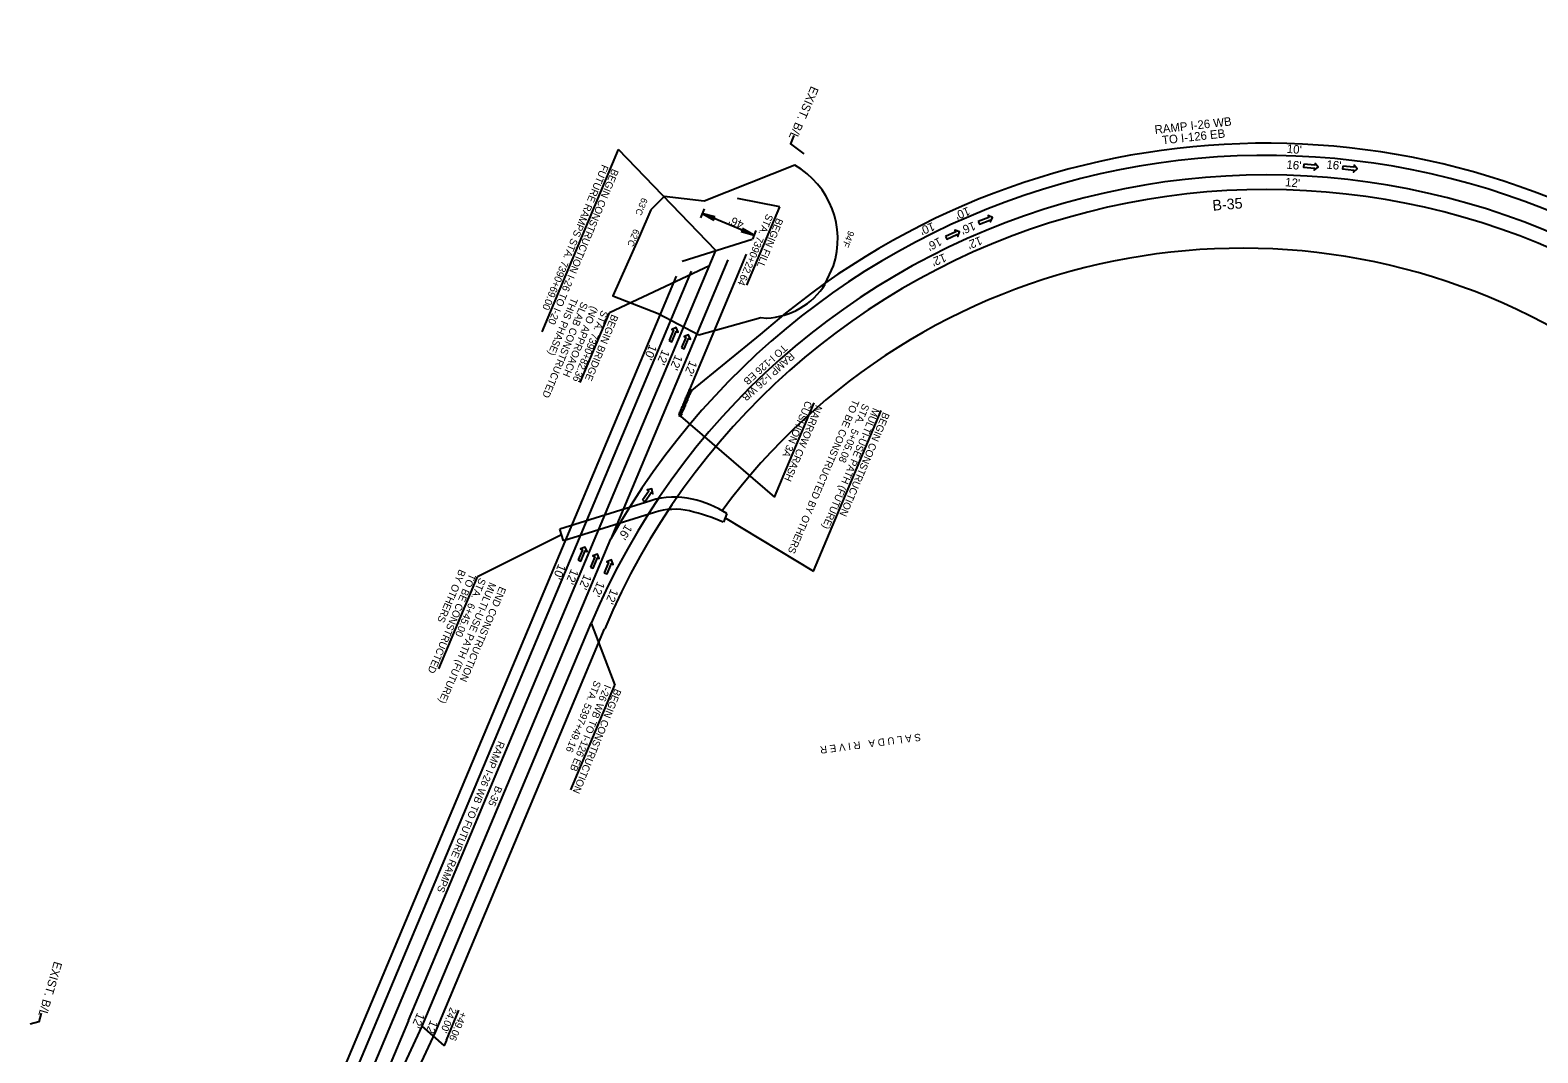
# Model space of a CAD drawing. Extents: x 1966090 to 1975830, y 788086 to 801233.
# Drawn here: x 1968411 to 1969648, y 796844 to 797683 of the extents above; entities that cross this region are included whole.
import ezdxf

# ---------------------------------------------------------------- set-up
doc = ezdxf.new("R2010")
doc.units = 0
for name, color, linetype in [('BR_PRESTRESSED BEAM', 7, 'Continuous'), ('BR_PROPOSED_DRAINAGE', 7, 'Continuous'), ('RD_EX_Driveway_txCode', 7, 'Continuous'), ('RD_EX_SU_Gas', 7, 'Continuous'), ('RD_EX_SU_H2O', 7, 'Continuous'), ('RD_EX_SU_SwpLmt', 7, 'Continuous'), ('RD_EX_TX_BldgApp_ELEV', 7, 'Continuous'), ('RD_EX_TX_Dam_ELEV', 7, 'Continuous'), ('RD_GT_Surcharge', 7, 'Continuous'), ('RD_PD_PaveShd', 7, 'Continuous'), ('RD_Sketch6', 7, 'Continuous'), ('RD_Sketch8', 7, 'Continuous')]:
    doc.layers.add(name, color=color, linetype=linetype)

msp = doc.modelspace()

# ---------------------------------------------------------------- linework, layer by layer
at = {"layer": 'BR_PRESTRESSED BEAM'}
msp.add_line((1968951.7, 797388.6), (1968953.5, 797387.8), dxfattribs=at)
at = {"layer": 'BR_PROPOSED_DRAINAGE'}
for p, q in [((1968931, 797546.9), (1968920.1, 797536)), ((1968920.1, 797536), (1968910.7, 797514.3)), ((1969063.1, 797475.1), (1969069.8, 797489.9)), ((1968926, 797450.8), (1968959.4, 797433.4))]:
    msp.add_line(p, q, dxfattribs=at)
for points in [[(1969038.3, 797572.5), (1968963.9, 797543.2), (1968931, 797546.9)], [(1968910.7, 797514.3), (1968888.9, 797465.3), (1968926, 797450.8)], [(1968959.4, 797433.4), (1969010.3, 797447.6), (1969015.1, 797447)]]:
    msp.add_lwpolyline(points, dxfattribs=at)
for centre, radius, start, end in [((1969003.7, 797512), 69.7, 341.4906, 60.2558), ((1969012.3, 797507), 60, 272.7088, 327.863)]:
    msp.add_arc(centre, radius, start, end, dxfattribs=at)
at = {"layer": 'RD_EX_Driveway_txCode'}
for p, q in [((1968963.9, 797536.7), (1968960.8, 797529.3)), ((1969004.8, 797515.2), (1968962.3, 797533)), ((1969006.3, 797518.9), (1969003.4, 797512))]:
    msp.add_line(p, q, dxfattribs=at)
for points in [[(1969455.6, 797573.4), (1969455.4, 797571), (1969464.5, 797570.1), (1969464.3, 797568.5), (1969467.4, 797571), (1969464.9, 797574.1), (1969464.7, 797572.5)], [(1969487.7, 797571.9), (1969487.4, 797569.5), (1969496.6, 797568.6), (1969496.4, 797567), (1969499.5, 797569.5), (1969497, 797572.6), (1969496.8, 797571)], [(1969188.7, 797526.5), (1969189.6, 797524.3), (1969198.1, 797527.6), (1969198.7, 797526.1), (1969200.3, 797529.8), (1969196.7, 797531.4), (1969197.3, 797529.8)], [(1969161.8, 797514.1), (1969162.8, 797511.9), (1969171.2, 797515.7), (1969171.8, 797514.2), (1969173.3, 797518), (1969169.5, 797519.4), (1969170.2, 797517.9)], [(1968935.2, 797428.7), (1968937.4, 797427.7), (1968941, 797436.2), (1968942.5, 797435.6), (1968941, 797439.3), (1968937.3, 797437.8), (1968938.8, 797437.1)], [(1968945.3, 797422.9), (1968947.5, 797421.9), (1968951, 797430.4), (1968952.5, 797429.8), (1968951, 797433.5), (1968947.3, 797431.9), (1968948.8, 797431.3)], [(1968913.3, 797297.6), (1968915.3, 797296.3), (1968920.4, 797303.9), (1968921.8, 797302.9), (1968921, 797306.9), (1968917.1, 797306.1), (1968918.4, 797305.2)], [(1968860.5, 797248.6), (1968862.7, 797247.7), (1968866.3, 797256.1), (1968867.8, 797255.5), (1968866.2, 797259.2), (1968862.5, 797257.7), (1968864, 797257)], [(1968870.6, 797242.8), (1968872.8, 797241.8), (1968876.3, 797250.3), (1968877.8, 797249.7), (1968876.3, 797253.4), (1968872.6, 797251.9), (1968874.1, 797251.2)], [(1968881.9, 797238), (1968884.2, 797237.1), (1968887.7, 797245.6), (1968889.2, 797244.9), (1968887.7, 797248.6), (1968884, 797247.1), (1968885.5, 797246.5)]]:
    msp.add_lwpolyline(points, close=True, dxfattribs=at)
at = {"layer": 'RD_EX_SU_Gas'}
for p, q in [((1968592.6, 796594.5), (1968973.4, 797502.5)), ((1968721.4, 796870.7), (1968887.2, 797265.9)), ((1968721.4, 796870.7), (1968605.4, 796594))]:
    msp.add_line(p, q, dxfattribs=at)
msp.add_arc((1981199.2, 806823), 14512, 217.23394, 219.56622, dxfattribs=at)
at = {"layer": 'RD_EX_TX_BldgApp_ELEV'}
for p, q in [((1968951.6, 797388.6), (1968950.9, 797386.1)), ((1968953.6, 797387.8), (1968951.6, 797388.6)), ((1968946.6, 797376.8), (1968946, 797374.3)), ((1968948.7, 797376), (1968946.6, 797376.8)), ((1968947.6, 797379.2), (1968947, 797376.7)), ((1968947, 797376.7), (1968948.3, 797376.1)), ((1968947.3, 797373.8), (1968948.7, 797376)), ((1968949.6, 797378.4), (1968947.6, 797379.2)), ((1968948.6, 797381.6), (1968948, 797379.1)), ((1968948, 797379.1), (1968949.3, 797378.5)), ((1968948.3, 797376.1), (1968949.6, 797378.4)), ((1968950.6, 797380.7), (1968948.6, 797381.6)), ((1968948.6, 797378.8), (1968948.6, 797378.8)), ((1968949.6, 797383.9), (1968948.9, 797381.4)), ((1968948.9, 797381.4), (1968950.3, 797380.9)), ((1968949.3, 797378.5), (1968950.6, 797380.7)), ((1968951.6, 797383.1), (1968949.6, 797383.9)), ((1968950.6, 797386.3), (1968949.9, 797383.8)), ((1968949.9, 797383.8), (1968951.3, 797383.2)), ((1968950.3, 797380.9), (1968951.6, 797383.1)), ((1968952.6, 797385.4), (1968950.6, 797386.3)), ((1968950.9, 797386.1), (1968952.3, 797385.6)), ((1968951.3, 797383.2), (1968952.6, 797385.4)), ((1968952.3, 797385.6), (1968953.6, 797387.8)), ((1968943.7, 797369.8), (1968943, 797367.3)), ((1968943, 797367.3), (1968944.4, 797366.7)), ((1968945.7, 797368.9), (1968943.7, 797369.8)), ((1968944.7, 797372.1), (1968944, 797369.6)), ((1968944, 797369.6), (1968945.4, 797369.1)), ((1968944.4, 797366.7), (1968945.7, 797368.9)), ((1968946.7, 797371.3), (1968944.7, 797372.1)), ((1968945.6, 797374.5), (1968945, 797372)), ((1968945, 797372), (1968946.3, 797371.4)), ((1968945.4, 797369.1), (1968946.7, 797371.3)), ((1968947.7, 797373.6), (1968945.6, 797374.5)), ((1968946, 797374.3), (1968947.3, 797373.8)), ((1968946.3, 797371.4), (1968947.7, 797373.6))]:
    msp.add_line(p, q, dxfattribs=at)
at = {"layer": 'RD_EX_TX_Dam_ELEV'}
msp.add_arc((1969405, 796974.4), 530, 59.3657, 143.5811, dxfattribs=at)
at = {"layer": 'RD_GT_Surcharge'}
for p, q in [((1968920.1, 797297.2), (1968845.5, 797273.9)), ((1968923, 797287.7), (1968848.4, 797264.4)), ((1968982.4, 797286.8), (1968979.6, 797279.6)), ((1968848.4, 797264.4), (1968845.5, 797273.9))]:
    msp.add_line(p, q, dxfattribs=at)
for centre, radius, start, end in [((1968939.5, 797235.2), 65, 77.0814, 107.3772), ((1968939.5, 797235.2), 55, 77.0814, 107.3772), ((1968933.5, 797209), 91.9, 57.7982, 77.0814), ((1968917.5, 797139.6), 153.1, 66.0948, 77.0814)]:
    msp.add_arc(centre, radius, start, end, dxfattribs=at)
at = {"layer": 'RD_PD_PaveShd'}
for p, q in [((1968998.2, 797499.5), (1968951.7, 797388.6)), ((1968940.8, 797481.5), (1968572.3, 796603)), ((1969009.8, 797433.6), (1968953.5, 797387.8)), ((1968953.5, 797387.8), (1968951.7, 797388.6)), ((1968743.5, 796861.2), (1968882.2, 797192)), ((1968616.2, 796588.8), (1968743.5, 796861.2))]:
    msp.add_line(p, q, dxfattribs=at)
for radius, end in [(626, 131.4818), (588, 157.246)]:
    msp.add_arc((1969424.5, 796964.6), radius, 54.7761, end, dxfattribs=at)
at = {"layer": 'RD_Sketch6'}
for p, q in [((1968831, 797435.9), (1968893.7, 797585.5)), ((1968973.4, 797502.5), (1968893.7, 797585.5)), ((1969025.8, 797538.3), (1968991.3, 797545.2)), ((1968998.9, 797474.2), (1969025.8, 797538.3)), ((1968962.3, 797533), (1968971.8, 797527.5)), ((1968972.9, 797530.1), (1968962.3, 797533)), ((1968971.4, 797529.2), (1968972.9, 797530.1)), ((1968971.8, 797527.5), (1968971.4, 797529.2)), ((1968995.7, 797519), (1968994.2, 797518.1)), ((1968994.2, 797518.1), (1969004.8, 797515.2)), ((1969004.8, 797515.2), (1968995.3, 797520.7)), ((1968995.3, 797520.7), (1968995.7, 797519)), ((1968945.9, 797493.9), (1969003.3, 797511.8)), ((1968968.2, 797490.1), (1968886.1, 797451.4)), ((1968862.1, 797394.2), (1968886.1, 797451.4)), ((1969021.5, 797300.1), (1969054, 797377.7)), ((1968944.4, 797366.7), (1969021.5, 797300.1)), ((1969053.6, 797239.4), (1969108.9, 797371.2)), ((1968981, 797283.3), (1969053.6, 797239.4)), ((1968846.9, 797269.1), (1968777.8, 797234.7)), ((1968746.1, 797159.3), (1968777.8, 797234.7)), ((1968871.2, 797196.7), (1968890.6, 797145.9)), ((1968854.6, 797059.9), (1968890.6, 797145.9)), ((1968752.4, 796854.6), (1968762.6, 796879))]:
    msp.add_line(p, q, dxfattribs=at)
for points in [[(1969037.5, 797597), (1969034.6, 797590), (1969045.7, 797581.9)], [(1968420.1, 796876.7), (1968418.1, 796869.5), (1968411, 796867.7)], [(1968752.4, 796854.6), (1968750.5, 796850.2), (1968732.5, 796866)]]:
    msp.add_lwpolyline(points, dxfattribs=at)
at = {"layer": 'RD_Sketch8'}
for p, q in [((1968983.2, 797494.8), (1968887.2, 797265.9)), ((1968953.2, 797485.5), (1968581.5, 796599.1)), ((1968732.5, 796866), (1968871.2, 797196.7)), ((1968605.4, 796594), (1968732.5, 796866))]:
    msp.add_line(p, q, dxfattribs=at)
for centre, radius, start, end in [((1981199.2, 806823), 14524, 217.23394, 219.56622), ((1969424.5, 796964.6), 616, 54.7761, 150.713), ((1969424.5, 796964.6), 600, 54.7761, 157.246)]:
    msp.add_arc(centre, radius, start, end, dxfattribs=at)

# ---------------------------------------------------------------- texts
at = {"layer": 'RD_EX_Driveway_txCode'}
for s, height, rotation, p in [("10'", 7, 354.7945, (1969441.5, 797582.8)), ("16'", 7, 354.7945, (1969441.2, 797569.8)), ("16'", 7, 354.7945, (1969474, 797569.8)), ("12'", 7, 354.7945, (1969440.1, 797555.4)), ("10'", 7, 201.8272, (1969180.2, 797538.6)), ('B-35', 8.75, 4.6963, (1969381.1, 797535.2)), ("46'", 7, 157.246, (1968997.1, 797526.3)), ("10'", 7, 201.8272, (1969151.3, 797526)), ("16'", 7, 201.8272, (1969184.8, 797526.5)), ("16'", 7, 207.175, (1969156.6, 797513.7)), ("12'", 7, 201.8272, (1969190.2, 797514.4)), ("12'", 7, 201.8272, (1969160.8, 797500.4)), ("10'", 7, 247.2476, (1968919.1, 797425.9)), ("12'", 7, 247.246, (1968929.5, 797421.8)), ("12'", 7, 247.246, (1968940.2, 797417.5)), ("12'", 7, 247.246, (1968952.1, 797412.8)), ("16'", 7, 238.7414, (1968899.5, 797278.4)), ("10'", 7, 247.2476, (1968844.4, 797245.8)), ("12'", 7, 247.246, (1968854.8, 797241.7)), ("12'", 7, 247.246, (1968865.5, 797237.4)), ("12'", 7, 247.246, (1968876.3, 797231.5)), ("12'", 7, 247.2476, (1968887.4, 797225.4)), ("12'", 7, 247.246, (1968728.6, 796877.6)), ("12'", 7, 247.2476, (1968739.5, 796871.4))]:
    msp.add_text(s, height=height, rotation=rotation, dxfattribs=at).set_placement(p)
at = {"layer": 'RD_EX_SU_H2O'}
for s, p in [('RAMP I-26 WB', (1969333.7, 797598.2)), ('TO I-126 EB', (1969339.8, 797589.6))]:
    msp.add_text(s, height=7, rotation=6.3882, dxfattribs=at).set_placement(p)
at = {"layer": 'RD_EX_SU_SwpLmt'}
for s, p in [("63'C", (1968912.8, 797546.3)), ("62'C", (1968906.2, 797520.7)), ("94'F", (1969082.3, 797519.3))]:
    msp.add_text(s, height=5.4, rotation=247.246, dxfattribs=at).set_placement(p)
at = {"layer": 'RD_Sketch6'}
for s, height, rotation, p in [('EXIST. B/L', 7, 246.4827, (1969051.6, 797638)), ('FUTURE RAMPS STA. 7390+69.00', 6, 247.4075, (1968880.1, 797573.6)), ('BEGIN CONSTRUCTION I-26 TO I-20 ', 6, 247.4075, (1968888.4, 797570.1)), ('STA. 7390+22.64', 6, 247.4075, (1969015.1, 797533.2)), ('BEGIN FILL', 6, 247.4075, (1969023.4, 797529.7)), ('SLAB CONSTRUCTED', 6, 247.4075, (1968863.2, 797460.9)), ('THIS PHASE)', 6, 247.4075, (1968854.9, 797464.4)), ('(NO APPROACH', 6, 247.4075, (1968871.5, 797457.5)), ('STA. 7390+82.36', 6, 247.4075, (1968879.8, 797454)), ('BEGIN BRIDGE ', 6, 247.4075, (1968888.1, 797450.6)), ('RAMP I-26 WB ', 6, 221.8685, (1969034.7, 797419.2)), ('TO I-126 EB ', 6, 221.8685, (1969028.7, 797425.9)), ('CUSHION 3A', 6, 246.9141, (1969047.2, 797379.7)), ('TO BE CONSTRUCTED BY OTHERS', 6, 246.9141, (1969085.8, 797380.9)), ('STA.  5+05.08', 6, 246.9141, (1969094.1, 797377.4)), ('NARROW CRASH', 6, 246.9141, (1969055.5, 797376.2)), ('MULTI-USE PATH (FUTURE)', 6, 246.9141, (1969102.4, 797373.9)), ('BEGIN CONSTRUCTION', 6, 246.9141, (1969110.7, 797370.4)), ('BY OTHERS', 6, 246.9141, (1968763, 797241.4)), ('TO BE CONSTRUCTED', 6, 246.9141, (1968771.3, 797237.9)), ('MULTI-USE PATH (FUTURE)', 6, 246.9141, (1968787.9, 797230.8)), ('STA.  6+45.00', 6, 246.9141, (1968779.6, 797234.4)), ('END CONSTRUCTION', 6, 246.9141, (1968796.1, 797227.3)), ('STA. 5397+49.16', 6, 247.717, (1968873.9, 797150.2)), ('I-26 WB TO I-126 EB', 6, 247.717, (1968882.3, 797146.8)), ('BEGIN CONSTRUCTION', 6, 247.717, (1968890.6, 797143.4)), ('S A L U D A   R I V E R', 6, 187.3795, (1969141.2, 797106.2)), ('RAMP I-26 WB TO FUTURE RAMPS', 6, 247.717, (1968795, 797100.5)), ('B-35', 6, 247.717, (1968792.9, 797063.7)), ('EXIST. B/L', 7, 253.6052, (1968430.7, 796919.6)), ("24.00'", 6, 247.246, (1968755.7, 796881.9)), ('+49.06', 6, 247.246, (1968764, 796878.4))]:
    msp.add_text(s, height=height, rotation=rotation, dxfattribs=at).set_placement(p)

doc.saveas('drawing.dxf')
